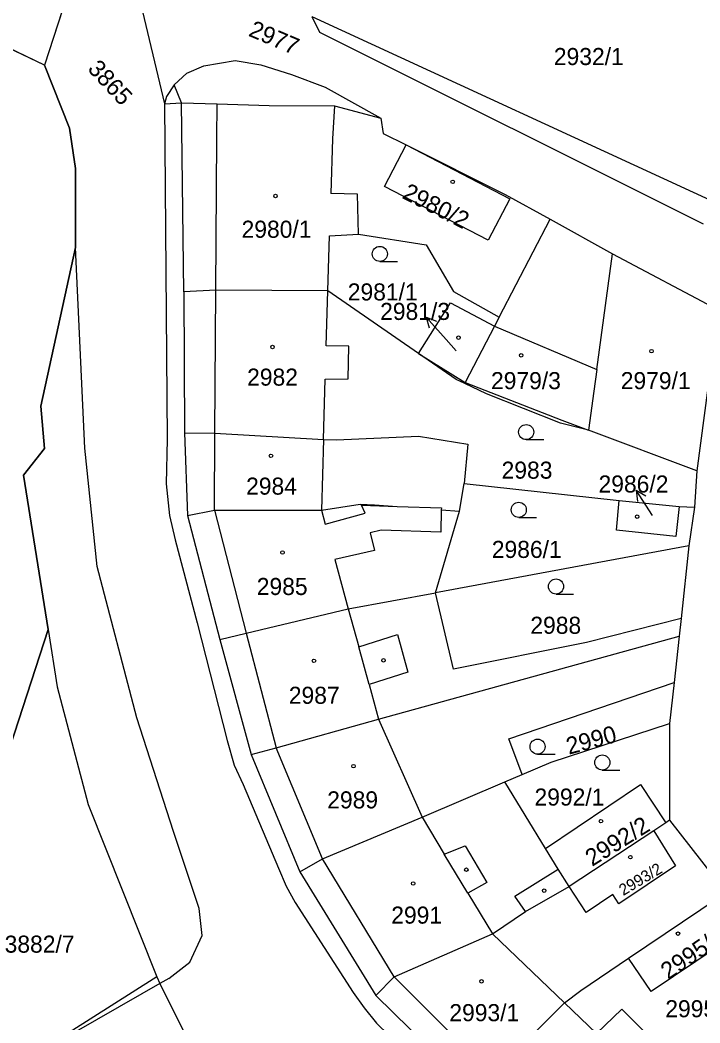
# Model space of a CAD drawing. Extents: x -527335 to -526256, y -1079142 to -1077809.
# Drawn here: x -526750.4 to -526682.7, y -1078714.2 to -1078614.4 of the extents above; entities that cross this region are included whole.
import ezdxf

# ---------------------------------------------------------------- set-up
doc = ezdxf.new("R2010")
doc.units = 0
for name, color, linetype in [('Vrstva 1', 7, 'Continuous'), ('Vrstva 2', 7, 'Continuous'), ('Vrstva 3', 7, 'Continuous'), ('Vrstva 4', 7, 'Continuous'), ('Vrstva 5', 7, 'Continuous'), ('Vrstva 54', 7, 'Continuous'), ('Vrstva 7', 7, 'Continuous')]:
    doc.layers.add(name, color=color, linetype=linetype)

msp = doc.modelspace()

# ---------------------------------------------------------------- linework, layer by layer
at = {"layer": 'Vrstva 1'}
for p, q in [((-526739.77, -1078606.94), (-526736.02, -1078622.71)), ((-526744.33, -1078607.7), (-526747.97, -1078618.86)), ((-526747.97, -1078618.86), (-526766.12, -1078610.17)), ((-526721.35, -1078614.01), (-526679.1, -1078633.49)), ((-526736.02, -1078622.71), (-526734.32, -1078622.61)), ((-526734.09, -1078641.43), (-526734.32, -1078622.61)), ((-526702.72, -1078643.94), (-526697.66, -1078634.2)), ((-526734.09, -1078641.43), (-526734.02, -1078655.45)), ((-526710.74, -1078647.55), (-526719.77, -1078641.31)), ((-526702.72, -1078643.94), (-526703.19, -1078644.85)), ((-526680.92, -1078643.22), (-526683.06, -1078659.24)), ((-526734.02, -1078655.45), (-526733.74, -1078663.69)), ((-526683.06, -1078659.24), (-526693.83, -1078655.18)), ((-526683.06, -1078659.24), (-526683.29, -1078662.87)), ((-526706.68, -1078663.24), (-526706.21, -1078660.51)), ((-526706.21, -1078660.51), (-526690.77, -1078662.18)), ((-526690.77, -1078662.18), (-526684.82, -1078662.79)), ((-526684.82, -1078662.79), (-526683.29, -1078662.87)), ((-526683.29, -1078662.87), (-526683.84, -1078666.72)), ((-526733.74, -1078663.69), (-526730.51, -1078676.04)), ((-526709.06, -1078671.38), (-526706.68, -1078663.24)), ((-526683.84, -1078666.72), (-526709.06, -1078671.38)), ((-526683.84, -1078666.72), (-526684.62, -1078673.95)), ((-526684.62, -1078673.95), (-526684.81, -1078675.69)), ((-526684.81, -1078675.69), (-526685.32, -1078680.32)), ((-526730.51, -1078676.04), (-526727.41, -1078687.49)), ((-526685.32, -1078680.32), (-526685.77, -1078684.4)), ((-526685.77, -1078684.4), (-526685.78, -1078694.02)), ((-526727.41, -1078687.49), (-526722.57, -1078699.16)), ((-526702.15, -1078690.19), (-526700.45, -1078689.46)), ((-526698.12, -1078696.82), (-526702.15, -1078690.19)), ((-526686.15, -1078694.26), (-526687.35, -1078695.06)), ((-526685.78, -1078694.02), (-526686.15, -1078694.26)), ((-526685.78, -1078694.02), (-526680.15, -1078701.23)), ((-526687.35, -1078695.06), (-526695.75, -1078700.62)), ((-526722.57, -1078699.16), (-526714.99, -1078711.45)), ((-526689.86, -1078707.76), (-526680.84, -1078701.69)), ((-526736.78, -1078709.62), (-526766.02, -1078728.13)), ((-526705.09, -1078721.19), (-526714.99, -1078711.45))]:
    msp.add_line(p, q, dxfattribs=at)
for points in [[(-526747.6, -1078675.03), (-526750.05, -1078659.68), (-526747.95, -1078657.02), (-526748.33, -1078652.79), (-526744.86, -1078637), (-526744.86, -1078629.16), (-526745.47, -1078625.12), (-526747.97, -1078618.86)], [(-526736.02, -1078622.71), (-526735.76, -1078656.09), (-526735.85, -1078660.53), (-526735.52, -1078663.69), (-526734.95, -1078666.12), (-526732.77, -1078674.37), (-526729.8, -1078686.09), (-526729.09, -1078688.53), (-526728.19, -1078690.47), (-526724.67, -1078698.8), (-526723.91, -1078700.57), (-526723.02, -1078702.2), (-526717.26, -1078711.17), (-526716.15, -1078712.7), (-526714.92, -1078714.22), (-526690.33, -1078738.18), (-526681.83, -1078746.32), (-526638.92, -1078788.12), (-526632.34, -1078794.49), (-526593.57, -1078832.2), (-526592.15, -1078831.2)], [(-526734.32, -1078622.61), (-526730.77, -1078622.72), (-526725.62, -1078622.89), (-526719.1, -1078622.92), (-526714.49, -1078624.12), (-526714.26, -1078625.67), (-526711.99, -1078626.8), (-526702.11, -1078631.73), (-526697.66, -1078634.2)], [(-526714.14, -1078630.93), (-526711.99, -1078626.8), (-526701.67, -1078632.15), (-526703.83, -1078636.29), (-526714.14, -1078630.93)], [(-526697.66, -1078634.2), (-526691.45, -1078637.64), (-526680.92, -1078643.22)], [(-526719.77, -1078641.31), (-526719.61, -1078635.84), (-526716.73, -1078635.68), (-526709.97, -1078636.74), (-526707.28, -1078641.39), (-526702.72, -1078643.94)], [(-526719.77, -1078641.31), (-526730.91, -1078641.27), (-526734.09, -1078641.43)], [(-526720.2, -1078656.11), (-526720.03, -1078650.11), (-526717.74, -1078650.09), (-526717.68, -1078646.84), (-526719.93, -1078646.81), (-526719.77, -1078641.31)], [(-526710.74, -1078647.55), (-526707.55, -1078642.52), (-526703.19, -1078644.85)], [(-526703.19, -1078644.85), (-526706.1, -1078650.46), (-526706.15, -1078650.55)], [(-526703.19, -1078644.85), (-526693.01, -1078649.14), (-526693.31, -1078651.32), (-526693.83, -1078655.18)], [(-526706.15, -1078650.55), (-526707, -1078650.14), (-526710.74, -1078647.55)], [(-526693.83, -1078655.18), (-526696.62, -1078654.48), (-526703.97, -1078651.59), (-526706.15, -1078650.55)], [(-526734.02, -1078655.45), (-526731, -1078655.49), (-526720.2, -1078656.11)], [(-526720.2, -1078656.11), (-526718.9, -1078656.16), (-526710.76, -1078655.78), (-526705.84, -1078656.59), (-526706.21, -1078660.51)], [(-526733.74, -1078663.69), (-526731.05, -1078663.17), (-526720.41, -1078663.15), (-526716.54, -1078662.56), (-526715.12, -1078662.61), (-526712.88, -1078662.78), (-526708.47, -1078662.91), (-526708.48, -1078663.11), (-526706.68, -1078663.24)], [(-526684.82, -1078662.79), (-526685.16, -1078665.77), (-526691.04, -1078665.14), (-526690.77, -1078662.18)], [(-526730.51, -1078676.04), (-526727.88, -1078675.39), (-526717.73, -1078672.98), (-526709.06, -1078671.38)], [(-526684.62, -1078673.95), (-526694.02, -1078676.34), (-526707.27, -1078678.98), (-526709.06, -1078671.38)], [(-526766.02, -1078728.13), (-526758.54, -1078708.63), (-526747.6, -1078675.03)], [(-526747.6, -1078675.03), (-526746.69, -1078680.74), (-526743.6, -1078692.45), (-526736.78, -1078709.62)], [(-526727.41, -1078687.49), (-526724.92, -1078686.81), (-526714.74, -1078683.95), (-526684.81, -1078675.69)], [(-526700.45, -1078689.46), (-526701.77, -1078685.93), (-526685.32, -1078680.32)], [(-526700.45, -1078689.46), (-526697.56, -1078688.23), (-526685.77, -1078684.4)], [(-526722.57, -1078699.16), (-526720.3, -1078697.87), (-526710.4, -1078693.71), (-526702.15, -1078690.19)], [(-526698.12, -1078696.82), (-526688.65, -1078690.47), (-526686.15, -1078694.26)], [(-526687.35, -1078695.06), (-526685.17, -1078698.54), (-526690.81, -1078702.35), (-526691.43, -1078701.42), (-526694.08, -1078703.21), (-526695.75, -1078700.62)], [(-526695.75, -1078700.62), (-526696.86, -1078698.9), (-526698.12, -1078696.82)], [(-526714.99, -1078711.45), (-526713.16, -1078709.62), (-526703.39, -1078705.34), (-526700.09, -1078703.11), (-526695.75, -1078700.62)], [(-526680.84, -1078701.69), (-526678.6, -1078705.01), (-526687.59, -1078711.07), (-526689.86, -1078707.76)], [(-526696.22, -1078712.19), (-526694.61, -1078710.96), (-526689.86, -1078707.76)], [(-526736.78, -1078709.62), (-526736.47, -1078710.26), (-526732.32, -1078718.67), (-526731.58, -1078720.17)], [(-526696.22, -1078712.19), (-526703.4, -1078719.37), (-526705.09, -1078721.19)], [(-526685.11, -1078719.62), (-526687.43, -1078717.35), (-526686.72, -1078716.65), (-526690.52, -1078712.81), (-526693.04, -1078715.23), (-526696.22, -1078712.19)]]:
    msp.add_lwpolyline(points, dxfattribs=at)
at = {"layer": 'Vrstva 3'}
for p, q in [((-526714.593, -1078638.4), (-526712.843, -1078638.4)), ((-526700.033, -1078656.13), (-526698.283, -1078656.13)), ((-526700.773, -1078663.87), (-526699.023, -1078663.87)), ((-526697.063, -1078671.5), (-526695.313, -1078671.5)), ((-526698.903, -1078687.44), (-526697.153, -1078687.44)), ((-526692.463, -1078689.02), (-526690.713, -1078689.02))]:
    msp.add_line(p, q, dxfattribs=at)
for centre in [(-526714.593, -1078637.65), (-526700.033, -1078655.38), (-526700.773, -1078663.12), (-526697.063, -1078670.75), (-526698.903, -1078686.69), (-526692.463, -1078688.27)]:
    msp.add_circle(centre, 0.75, dxfattribs=at)
at = {"layer": 'Vrstva 4'}
for p, q in [((-526721.35, -1078614.01), (-526720.61, -1078615.59)), ((-526720.61, -1078615.59), (-526682.42, -1078634.66)), ((-526733.8, -1078619.65), (-526732.12, -1078618.91)), ((-526732.12, -1078618.91), (-526729, -1078618.39)), ((-526729, -1078618.39), (-526726.45, -1078618.83)), ((-526726.45, -1078618.83), (-526723.38, -1078619.8)), ((-526735.05, -1078620.83), (-526733.8, -1078619.65)), ((-526723.38, -1078619.8), (-526720.03, -1078621.04)), ((-526735.05, -1078620.83), (-526735.82, -1078621.98)), ((-526734.32, -1078622.61), (-526735.05, -1078620.83)), ((-526735.82, -1078621.98), (-526736.02, -1078622.71)), ((-526720.03, -1078621.04), (-526714.49, -1078624.12)), ((-526730.82, -1078626.16), (-526730.77, -1078622.72)), ((-526719.1, -1078622.92), (-526719.32, -1078626.18)), ((-526730.91, -1078641.27), (-526730.82, -1078626.16)), ((-526719.32, -1078626.18), (-526719.48, -1078631.65)), ((-526716.82, -1078631.7), (-526719.48, -1078631.65)), ((-526716.73, -1078635.68), (-526716.82, -1078631.7)), ((-526743.96, -1078656.98), (-526744.86, -1078637)), ((-526693.01, -1078649.14), (-526691.45, -1078637.64)), ((-526731, -1078655.49), (-526730.91, -1078641.27)), ((-526710.74, -1078647.55), (-526706.1, -1078650.46)), ((-526706.1, -1078650.46), (-526696.49, -1078654.18)), ((-526696.49, -1078654.18), (-526693.83, -1078655.18)), ((-526731.05, -1078663.17), (-526731, -1078655.49)), ((-526720.2, -1078656.11), (-526720.41, -1078663.15)), ((-526742.73, -1078668.75), (-526743.96, -1078656.98)), ((-526716.06, -1078663.45), (-526716.43, -1078662.67)), ((-526716.43, -1078662.67), (-526712.88, -1078662.78)), ((-526731.05, -1078663.17), (-526727.88, -1078675.39)), ((-526720.41, -1078663.15), (-526720.03, -1078664.56)), ((-526720.03, -1078664.56), (-526716.06, -1078663.45)), ((-526708.48, -1078663.11), (-526708.54, -1078665.33)), ((-526714.45, -1078665.16), (-526715.56, -1078665.4)), ((-526715.56, -1078665.4), (-526715.11, -1078667.16)), ((-526708.54, -1078665.33), (-526714.45, -1078665.16)), ((-526715.11, -1078667.16), (-526719.07, -1078668.07)), ((-526738.77, -1078683.83), (-526742.73, -1078668.75)), ((-526719.07, -1078668.07), (-526717.73, -1078672.98)), ((-526717.73, -1078672.98), (-526716.7, -1078676.75)), ((-526727.88, -1078675.39), (-526724.92, -1078686.81)), ((-526716.7, -1078676.75), (-526712.84, -1078675.54)), ((-526712.84, -1078675.54), (-526711.82, -1078679.28)), ((-526715.67, -1078680.52), (-526716.7, -1078676.75)), ((-526711.82, -1078679.28), (-526715.67, -1078680.52)), ((-526715.67, -1078680.52), (-526714.74, -1078683.95)), ((-526735.12, -1078695.13), (-526738.77, -1078683.83)), ((-526714.74, -1078683.95), (-526710.4, -1078693.71)), ((-526720.3, -1078697.87), (-526724.92, -1078686.81)), ((-526710.4, -1078693.71), (-526708.18, -1078697.39)), ((-526732.58, -1078702.79), (-526735.12, -1078695.13)), ((-526708.18, -1078697.39), (-526706.12, -1078696.55)), ((-526706.12, -1078696.55), (-526703.94, -1078700.21)), ((-526705.84, -1078701.28), (-526708.18, -1078697.39)), ((-526713.16, -1078709.62), (-526720.3, -1078697.87)), ((-526701.17, -1078701.58), (-526696.86, -1078698.9)), ((-526703.94, -1078700.21), (-526705.84, -1078701.28)), ((-526705.84, -1078701.28), (-526703.39, -1078705.34)), ((-526700.09, -1078703.11), (-526701.17, -1078701.58)), ((-526732.26, -1078705.49), (-526732.58, -1078702.79)), ((-526733.5, -1078708.13), (-526732.26, -1078705.49)), ((-526696.22, -1078712.19), (-526703.39, -1078705.34)), ((-526735.6, -1078709.76), (-526733.5, -1078708.13)), ((-526735.6, -1078709.76), (-526736.47, -1078710.26)), ((-526713.16, -1078709.62), (-526703.4, -1078719.37)), ((-526736.47, -1078710.26), (-526738.29, -1078711.31)), ((-526738.29, -1078711.31), (-526747.88, -1078716.79))]:
    msp.add_line(p, q, dxfattribs=at)
at = {"layer": 'Vrstva 5'}
for centre in [(-526707.347, -1078630.479), (-526724.977, -1078631.889), (-526706.767, -1078645.979), (-526725.277, -1078646.909), (-526700.527, -1078647.739), (-526687.567, -1078647.329), (-526725.427, -1078657.739), (-526688.997, -1078663.809), (-526724.277, -1078667.369), (-526721.147, -1078678.149), (-526714.237, -1078678.109), (-526717.217, -1078688.629), (-526692.597, -1078694.109), (-526689.667, -1078697.699), (-526705.987, -1078698.939), (-526711.277, -1078700.319), (-526698.247, -1078701.019), (-526684.926, -1078705.303), (-526704.477, -1078710.049)]:
    msp.add_circle(centre, 0.175, dxfattribs=at)
at = {"layer": 'Vrstva 54'}
for points in [[(-526703.39, -1078543.02), (-526715.41, -1078561.03), (-526728.83, -1078581.13), (-526744.33, -1078607.7), (-526747.97, -1078618.86), (-526766.12, -1078610.17), (-526763.31, -1078600.18), (-526763.05, -1078599.24), (-526753.29, -1078556.18), (-526750.73, -1078522.13), (-526753.35, -1078482.54), (-526753.77, -1078479.82), (-526755.3, -1078470.16), (-526758.4, -1078472.62), (-526766.27, -1078446.58), (-526780.95, -1078423.56)], [(-526747.97, -1078618.86), (-526745.47, -1078625.12), (-526744.86, -1078629.16), (-526744.86, -1078637), (-526748.33, -1078652.79), (-526747.95, -1078657.02), (-526750.05, -1078659.68), (-526747.6, -1078675.03), (-526758.54, -1078708.63)]]:
    msp.add_lwpolyline(points, dxfattribs=at)
at = {"layer": 'Vrstva 7'}
for p, q in [((-526707.99, -1078646.16), (-526709.998, -1078643.93)), ((-526709.998, -1078643.93), (-526708.956, -1078644.339)), ((-526709.998, -1078643.93), (-526709.7, -1078645.009)), ((-526706.99, -1078647.28), (-526707.99, -1078646.16)), ((-526687.46, -1078663.68), (-526689.094, -1078661.163)), ((-526689.094, -1078661.163), (-526688.129, -1078661.73)), ((-526689.094, -1078661.163), (-526688.969, -1078662.276))]:
    msp.add_line(p, q, dxfattribs=at)

# ---------------------------------------------------------------- texts
at = {"layer": 'Vrstva 2'}
for s, height, rotation, p in [('2977', 1.7, 337, (-526727.751, -1078615.913)), ('3865', 1.7, 313, (-526743.751, -1078619.304)), ('2980/2', 1.7, 333, (-526712.475, -1078632.047)), ('2990', 1.7, 15, (-526695.79, -1078687.501)), ('2992/2', 1.7, 32, (-526693.472, -1078698.662)), ('2993/2', 1.14, 31, (-526690.376, -1078701.568)), ('2995/2', 1.7, 34, (-526685.915, -1078709.943))]:
    msp.add_text(s, height=height, rotation=rotation, dxfattribs=at).set_placement(p)
for s, p in [('2932/1', (-526697.28, -1078618.85)), ('2980/1', (-526728.35, -1078636.04)), ('2981/1', (-526717.785, -1078642.28)), ('2981/3', (-526714.565, -1078644.22)), ('2982', (-526727.8, -1078650.76)), ('2979/3', (-526703.535, -1078651.11)), ('2979/1', (-526690.625, -1078651.11)), ('2983', (-526702.48, -1078660.02)), ('2984', (-526727.9, -1078661.61)), ('2986/2', (-526692.835, -1078661.4)), ('2986/1', (-526703.455, -1078667.91)), ('2985', (-526726.839, -1078671.6)), ('2988', (-526699.62, -1078675.46)), ('2987', (-526723.65, -1078682.43)), ('2992/1', (-526699.205, -1078692.56)), ('2989', (-526719.829, -1078692.84)), ('2991', (-526713.459, -1078704.31)), ('3882/7', (-526751.925, -1078707.2)), ('2993/1', (-526707.68, -1078714.02)), ('2995/1', (-526686.195, -1078713.63))]:
    msp.add_text(s, height=1.7, dxfattribs=at).set_placement(p)

doc.saveas('drawing.dxf')
